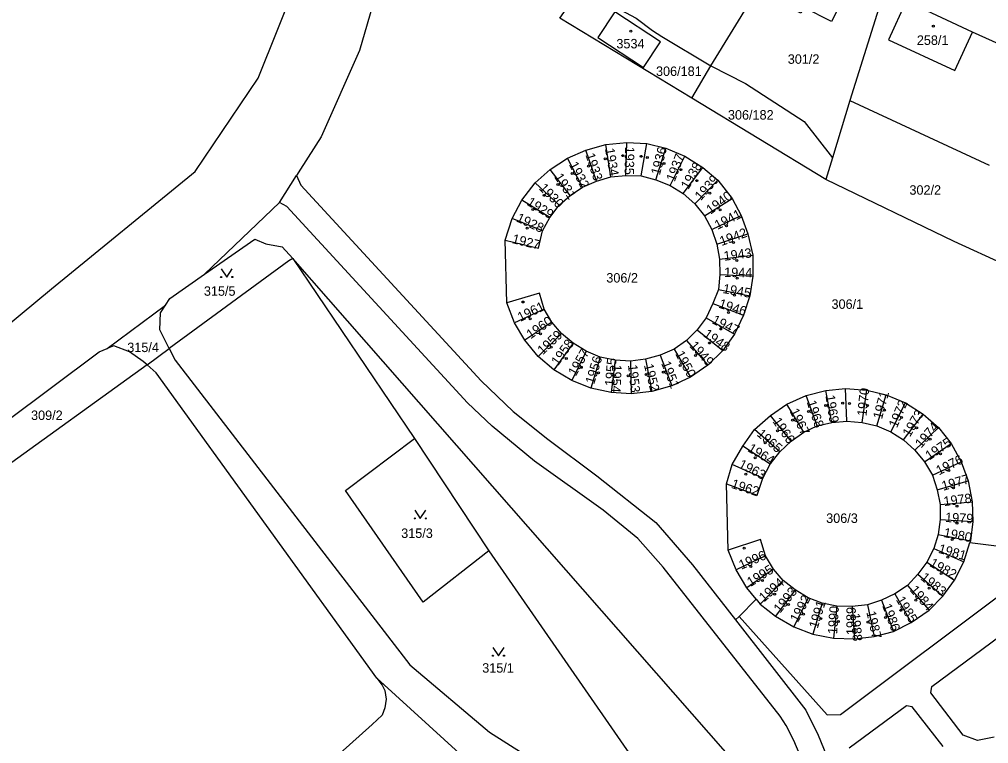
# Model space of a CAD drawing. Extents: x -679220 to -673243, y -1075091 to -1066557.
# Drawn here: x -676420.8 to -676246.6, y -1072425.2 to -1072295.1 of the extents above; entities that cross this region are included whole.
import ezdxf

# ---------------------------------------------------------------- set-up
doc = ezdxf.new("R2010")
doc.units = 0
for name, color, linetype in [('Hranice parcel', 7, 'Continuous'), ('Parcelní čísla', 7, 'Continuous'), ('Vnitřní kresba', 7, 'Continuous'), ('Značky budov', 7, 'Continuous'), ('Značky kultur', 7, 'Continuous')]:
    doc.layers.add(name, color=color, linetype=linetype)

msp = doc.modelspace()

# ---------------------------------------------------------------- linework, layer by layer
at = {"layer": 'Hranice parcel'}
for p, q in [((-676296.48, -1072303.48), (-676279.94, -1072276.36)), ((-676265.34, -1072290.05), (-676271.52, -1072309.71)), ((-676299.9, -1072309.29), (-676296.48, -1072303.48)), ((-676275.84, -1072323.88), (-676299.9, -1072309.29)), ((-676271.52, -1072309.71), (-676274.64, -1072320.01)), ((-676271.52, -1072309.71), (-676246.44, -1072321.34)), ((-676318.98, -1072318.61), (-676315.36, -1072317.62)), ((-676315.36, -1072317.62), (-676311.63, -1072317.26)), ((-676314.48, -1072323.42), (-676315.36, -1072317.62)), ((-676311.78, -1072323.16), (-676311.63, -1072317.26)), ((-676311.63, -1072317.26), (-676308.03, -1072317.42)), ((-676309.05, -1072323.25), (-676308.03, -1072317.42)), ((-676308.03, -1072317.42), (-676304.61, -1072318.29)), ((-676322.27, -1072320.05), (-676318.98, -1072318.61)), ((-676317.08, -1072324.2), (-676318.98, -1072318.61)), ((-676306.38, -1072323.96), (-676304.61, -1072318.29)), ((-676304.61, -1072318.29), (-676301.15, -1072319.7)), ((-676303.8, -1072324.98), (-676301.15, -1072319.7)), ((-676301.15, -1072319.7), (-676297.97, -1072321.71)), ((-676325.36, -1072322.08), (-676322.27, -1072320.05)), ((-676319.56, -1072325.3), (-676322.27, -1072320.05)), ((-676301.46, -1072326.41), (-676297.97, -1072321.71)), ((-676297.97, -1072321.71), (-676295.25, -1072324.04)), ((-676274.64, -1072320.01), (-676275.84, -1072323.88)), ((-676374.02, -1072328.04), (-676370.96, -1072323.19)), ((-676328.06, -1072324.5), (-676325.36, -1072322.08)), ((-676321.78, -1072326.75), (-676325.36, -1072322.08)), ((-676317.08, -1072324.2), (-676314.48, -1072323.42)), ((-676314.48, -1072323.42), (-676311.78, -1072323.16)), ((-676311.78, -1072323.16), (-676309.05, -1072323.25)), ((-676309.05, -1072323.25), (-676306.38, -1072323.96)), ((-676330.46, -1072327.6), (-676328.06, -1072324.5)), ((-676323.78, -1072328.52), (-676328.06, -1072324.5)), ((-676319.56, -1072325.3), (-676317.08, -1072324.2)), ((-676306.38, -1072323.96), (-676303.8, -1072324.98)), ((-676303.8, -1072324.98), (-676301.46, -1072326.41)), ((-676299.4, -1072328.29), (-676295.25, -1072324.04)), ((-676295.25, -1072324.04), (-676292.66, -1072327.28)), ((-676323.78, -1072328.52), (-676321.78, -1072326.75)), ((-676321.78, -1072326.75), (-676319.56, -1072325.3)), ((-676301.46, -1072326.41), (-676299.4, -1072328.29)), ((-676387.5, -1072340.91), (-676374.02, -1072328.04)), ((-676332.24, -1072330.91), (-676330.46, -1072327.6)), ((-676325.42, -1072330.7), (-676330.46, -1072327.6)), ((-676325.42, -1072330.7), (-676323.78, -1072328.52)), ((-676299.4, -1072328.29), (-676297.65, -1072330.43)), ((-676297.65, -1072330.43), (-676292.66, -1072327.28)), ((-676292.66, -1072327.28), (-676291.02, -1072330.35)), ((-676297.65, -1072330.43), (-676296.34, -1072332.88)), ((-676296.34, -1072332.88), (-676291.02, -1072330.35)), ((-676291.02, -1072330.35), (-676289.87, -1072333.63)), ((-676333.48, -1072334.78), (-676332.24, -1072330.91)), ((-676326.76, -1072333.1), (-676332.24, -1072330.91)), ((-676326.76, -1072333.1), (-676325.42, -1072330.7)), ((-676296.34, -1072332.88), (-676295.45, -1072335.51)), ((-676295.45, -1072335.51), (-676289.87, -1072333.63)), ((-676289.87, -1072333.63), (-676288.95, -1072337.48)), ((-676333.18, -1072346.04), (-676333.48, -1072334.78)), ((-676295.45, -1072335.51), (-676294.94, -1072338.2)), ((-676371.63, -1072338.06), (-676349.77, -1072370.44)), ((-676294.94, -1072338.2), (-676288.95, -1072337.48)), ((-676294.94, -1072338.2), (-676294.88, -1072340.96)), ((-676288.95, -1072337.48), (-676288.94, -1072341.24)), ((-676294.88, -1072340.96), (-676295.1, -1072343.67)), ((-676294.88, -1072340.96), (-676288.94, -1072341.24)), ((-676288.94, -1072341.24), (-676289.52, -1072344.81)), ((-676295.1, -1072343.67), (-676296.14, -1072346.19)), ((-676295.1, -1072343.67), (-676289.52, -1072344.81)), ((-676331.8, -1072349.66), (-676333.18, -1072346.04)), ((-676289.52, -1072344.81), (-676290.61, -1072348.27)), ((-676405.02, -1072354.26), (-676394.51, -1072346.45)), ((-676326.44, -1072347.2), (-676331.8, -1072349.66)), ((-676325.07, -1072349.54), (-676326.44, -1072347.2)), ((-676296.14, -1072346.19), (-676297.35, -1072348.76)), ((-676296.14, -1072346.19), (-676290.61, -1072348.27)), ((-676325.07, -1072349.54), (-676329.93, -1072352.76)), ((-676323.33, -1072351.59), (-676325.07, -1072349.54)), ((-676297.35, -1072348.76), (-676298.94, -1072350.92)), ((-676297.35, -1072348.76), (-676292.22, -1072351.69)), ((-676290.61, -1072348.27), (-676292.22, -1072351.69)), ((-676329.93, -1072352.76), (-676331.8, -1072349.66)), ((-676298.94, -1072350.92), (-676300.9, -1072352.8)), ((-676298.94, -1072350.92), (-676294.36, -1072354.59)), ((-676327.55, -1072355.72), (-676329.93, -1072352.76)), ((-676323.33, -1072351.59), (-676327.55, -1072355.72)), ((-676321.27, -1072353.32), (-676323.33, -1072351.59)), ((-676300.9, -1072352.8), (-676303.1, -1072354.36)), ((-676300.9, -1072352.8), (-676297.07, -1072357.27)), ((-676292.22, -1072351.69), (-676294.36, -1072354.59)), ((-676397.84, -1072357.19), (-676393.87, -1072354.27)), ((-676321.27, -1072353.32), (-676324.71, -1072358.08)), ((-676318.93, -1072354.76), (-676321.52, -1072360.01)), ((-676318.93, -1072354.76), (-676321.27, -1072353.32)), ((-676316.39, -1072355.82), (-676318.93, -1072354.76)), ((-676303.1, -1072354.36), (-676305.61, -1072355.45)), ((-676303.1, -1072354.36), (-676300.15, -1072359.43)), ((-676294.36, -1072354.59), (-676297.07, -1072357.27)), ((-676324.71, -1072358.08), (-676327.55, -1072355.72)), ((-676316.39, -1072355.82), (-676318.08, -1072361.39)), ((-676313.71, -1072356.38), (-676316.39, -1072355.82)), ((-676313.71, -1072356.38), (-676314.41, -1072362.17)), ((-676310.96, -1072356.51), (-676313.71, -1072356.38)), ((-676308.24, -1072356.2), (-676310.96, -1072356.51)), ((-676310.96, -1072356.51), (-676310.82, -1072362.38)), ((-676305.61, -1072355.45), (-676308.24, -1072356.2)), ((-676308.24, -1072356.2), (-676307.09, -1072362)), ((-676305.61, -1072355.45), (-676303.5, -1072360.95)), ((-676397.84, -1072357.19), (-676435.06, -1072384.05)), ((-676321.52, -1072360.01), (-676324.71, -1072358.08)), ((-676297.07, -1072357.27), (-676300.15, -1072359.43)), ((-676318.08, -1072361.39), (-676321.52, -1072360.01)), ((-676300.15, -1072359.43), (-676303.5, -1072360.95)), ((-676314.41, -1072362.17), (-676318.08, -1072361.39)), ((-676303.5, -1072360.95), (-676307.09, -1072362)), ((-676279.34, -1072362.68), (-676275.83, -1072361.78)), ((-676275.83, -1072361.78), (-676272.28, -1072361.47)), ((-676274.74, -1072367.56), (-676275.83, -1072361.78)), ((-676272.28, -1072361.47), (-676268.46, -1072361.73)), ((-676272.06, -1072367.32), (-676272.28, -1072361.47)), ((-676269.31, -1072367.55), (-676268.46, -1072361.73)), ((-676268.46, -1072361.73), (-676264.98, -1072362.57)), ((-676310.82, -1072362.38), (-676314.41, -1072362.17)), ((-676307.09, -1072362), (-676310.82, -1072362.38)), ((-676282.82, -1072364.28), (-676279.34, -1072362.68)), ((-676277.37, -1072368.16), (-676279.34, -1072362.68)), ((-676266.64, -1072368.15), (-676264.98, -1072362.57)), ((-676264.98, -1072362.57), (-676261.5, -1072364.04)), ((-676285.77, -1072366.32), (-676282.82, -1072364.28)), ((-676279.78, -1072369.31), (-676282.82, -1072364.28)), ((-676264.16, -1072369.22), (-676261.5, -1072364.04)), ((-676261.5, -1072364.04), (-676258.31, -1072366.06)), ((-676288.65, -1072368.81), (-676285.77, -1072366.32)), ((-676282.08, -1072370.89), (-676285.77, -1072366.32)), ((-676261.87, -1072370.68), (-676258.31, -1072366.06)), ((-676258.31, -1072366.06), (-676255.55, -1072368.47)), ((-676279.78, -1072369.31), (-676277.37, -1072368.16)), ((-676277.37, -1072368.16), (-676274.74, -1072367.56)), ((-676274.74, -1072367.56), (-676272.06, -1072367.32)), ((-676272.06, -1072367.32), (-676269.31, -1072367.55)), ((-676269.31, -1072367.55), (-676266.64, -1072368.15)), ((-676266.64, -1072368.15), (-676264.16, -1072369.22)), ((-676259.81, -1072372.52), (-676255.55, -1072368.47)), ((-676255.55, -1072368.47), (-676253.28, -1072371.33)), ((-676349.77, -1072370.44), (-676336.42, -1072390.58)), ((-676290.72, -1072371.82), (-676288.65, -1072368.81)), ((-676284.1, -1072372.82), (-676288.65, -1072368.81)), ((-676282.08, -1072370.89), (-676279.78, -1072369.31)), ((-676264.16, -1072369.22), (-676261.87, -1072370.68)), ((-676292.64, -1072375.1), (-676290.72, -1072371.82)), ((-676285.82, -1072375.04), (-676290.72, -1072371.82)), ((-676284.1, -1072372.82), (-676282.08, -1072370.89)), ((-676261.87, -1072370.68), (-676259.81, -1072372.52)), ((-676258.12, -1072374.62), (-676253.28, -1072371.33)), ((-676253.28, -1072371.33), (-676251.48, -1072374.61)), ((-676285.82, -1072375.04), (-676284.1, -1072372.82)), ((-676259.81, -1072372.52), (-676258.12, -1072374.62)), ((-676293.7, -1072378.59), (-676292.64, -1072375.1)), ((-676287.13, -1072377.56), (-676292.64, -1072375.1)), ((-676287.13, -1072377.56), (-676285.82, -1072375.04)), ((-676258.12, -1072374.62), (-676256.67, -1072377.02)), ((-676256.67, -1072377.02), (-676251.48, -1072374.61)), ((-676251.48, -1072374.61), (-676250.24, -1072378.06)), ((-676256.67, -1072377.02), (-676255.84, -1072379.62)), ((-676293.4, -1072390.49), (-676293.7, -1072378.59)), ((-676255.84, -1072379.62), (-676250.24, -1072378.06)), ((-676250.24, -1072378.06), (-676249.5, -1072381.78)), ((-676255.84, -1072379.62), (-676255.28, -1072382.29)), ((-676255.28, -1072382.29), (-676249.5, -1072381.78)), ((-676255.28, -1072382.29), (-676255.28, -1072384.95)), ((-676249.5, -1072381.78), (-676249.38, -1072385.33)), ((-676255.28, -1072384.95), (-676255.61, -1072387.66)), ((-676255.28, -1072384.95), (-676249.38, -1072385.33)), ((-676249.38, -1072385.33), (-676249.83, -1072388.83)), ((-676255.61, -1072387.66), (-676256.44, -1072390.2)), ((-676255.61, -1072387.66), (-676249.83, -1072388.83)), ((-676251.04, -1072392.6), (-676249.92, -1072389.1)), ((-676249.83, -1072388.83), (-676249.92, -1072389.1)), ((-676336.42, -1072390.58), (-676286.47, -1072462.64)), ((-676291.97, -1072394.03), (-676293.4, -1072390.49)), ((-676256.44, -1072390.2), (-676257.7, -1072392.66)), ((-676256.44, -1072390.2), (-676251.04, -1072392.6)), ((-676286.69, -1072391.5), (-676291.97, -1072394.03)), ((-676285.21, -1072393.89), (-676286.69, -1072391.5)), ((-676257.7, -1072392.66), (-676259.3, -1072394.78)), ((-676257.7, -1072392.66), (-676252.72, -1072395.87)), ((-676252.72, -1072395.87), (-676251.04, -1072392.6)), ((-676290.01, -1072397.25), (-676291.97, -1072394.03)), ((-676285.21, -1072393.89), (-676290.01, -1072397.25)), ((-676283.5, -1072395.94), (-676285.21, -1072393.89)), ((-676259.3, -1072394.78), (-676261.16, -1072396.82)), ((-676259.3, -1072394.78), (-676254.82, -1072398.74)), ((-676283.5, -1072395.94), (-676287.64, -1072400.19)), ((-676281.34, -1072397.61), (-676283.5, -1072395.94)), ((-676254.82, -1072398.74), (-676252.72, -1072395.87)), ((-676288.34, -1072399.32), (-676290.01, -1072397.25)), ((-676281.34, -1072397.61), (-676284.85, -1072402.35)), ((-676279.03, -1072399.03), (-676281.34, -1072397.61)), ((-676263.41, -1072398.36), (-676265.82, -1072399.49)), ((-676261.16, -1072396.82), (-676263.41, -1072398.36)), ((-676263.41, -1072398.36), (-676260.47, -1072403.46)), ((-676261.16, -1072396.82), (-676257.27, -1072401.26)), ((-676288.34, -1072399.32), (-676287.64, -1072400.19)), ((-676279.03, -1072399.03), (-676281.6, -1072404.26)), ((-676276.49, -1072400.02), (-676279.03, -1072399.03)), ((-676276.49, -1072400.02), (-676278.14, -1072405.57)), ((-676273.86, -1072400.57), (-676276.49, -1072400.02)), ((-676265.82, -1072399.49), (-676268.36, -1072400.32)), ((-676265.82, -1072399.49), (-676263.66, -1072405.07)), ((-676257.27, -1072401.26), (-676254.82, -1072398.74)), ((-676287.64, -1072400.19), (-676284.85, -1072402.35)), ((-676273.86, -1072400.57), (-676274.47, -1072406.28)), ((-676271.12, -1072400.61), (-676273.86, -1072400.57)), ((-676268.36, -1072400.32), (-676271.12, -1072400.61)), ((-676271.12, -1072400.61), (-676270.7, -1072406.4)), ((-676268.36, -1072400.32), (-676267.11, -1072406)), ((-676260.47, -1072403.46), (-676257.27, -1072401.26)), ((-676284.85, -1072402.35), (-676281.6, -1072404.26)), ((-676263.66, -1072405.07), (-676260.47, -1072403.46)), ((-676281.6, -1072404.26), (-676278.14, -1072405.57)), ((-676267.11, -1072406), (-676263.66, -1072405.07)), ((-676278.14, -1072405.57), (-676274.47, -1072406.28)), ((-676274.47, -1072406.28), (-676270.7, -1072406.4)), ((-676270.7, -1072406.4), (-676267.11, -1072406))]:
    msp.add_line(p, q, dxfattribs=at)
for points in [[(-676434.8, -1072359.89), (-676415.01, -1072343.53), (-676389.18, -1072322.47), (-676377.87, -1072305.66), (-676370.95, -1072288.33), (-676368.5, -1072263.86), (-676369.03, -1072238.4), (-676368.85, -1072231.56)], [(-676355.2, -1072271.06), (-676355.48, -1072281.26), (-676356.89, -1072291.18), (-676359.65, -1072300.73), (-676366.57, -1072316.22), (-676370.28, -1072322.02), (-676370.96, -1072323.19)], [(-676284.03, -1072290.85), (-676280.05, -1072282.92), (-676270.81, -1072287.62), (-676274.78, -1072295.52), (-676279.8, -1072293), (-676280.32, -1072294.03), (-676284.52, -1072291.87), (-676284.03, -1072290.85)], [(-676318.7, -1072287.76), (-676318.16, -1072290.47), (-676309.95, -1072294.91), (-676306.99, -1072297.14), (-676305.31, -1072298.18), (-676296.48, -1072303.48)], [(-676299.9, -1072309.29), (-676323.62, -1072294.93), (-676319.41, -1072288.79)], [(-676237.77, -1072302.43), (-676239.53, -1072301.48), (-676239.46, -1072301.35), (-676240.22, -1072300.78), (-676240.55, -1072300.65), (-676241.08, -1072301.17), (-676249.44, -1072297.41), (-676261.36, -1072291.87), (-676263.81, -1072290.74), (-676265.34, -1072290.05)], [(-676308.61, -1072303.77), (-676305.53, -1072299.16), (-676313.77, -1072293.75), (-676316.81, -1072298.4), (-676308.61, -1072303.77)], [(-676296.48, -1072303.48), (-676290.27, -1072306.64), (-676279.7, -1072313.49), (-676274.64, -1072320.01)], [(-676370.96, -1072323.19), (-676370.19, -1072324.92), (-676337.76, -1072360.05), (-676332.05, -1072365.58), (-676325.8, -1072370.56), (-676316.98, -1072377.11), (-676306.39, -1072385.49), (-676299.77, -1072393.11), (-676292.07, -1072402.99)], [(-676243.59, -1072339.2), (-676252.73, -1072335.04), (-676275.84, -1072323.88)], [(-676240.63, -1072470.5), (-676259.07, -1072453.6), (-676261.24, -1072451.54), (-676262.68, -1072450.14), (-676275.53, -1072436.12), (-676276.14, -1072435.29), (-676278.28, -1072431.93), (-676280.47, -1072427.4), (-676281.58, -1072424.69), (-676282.94, -1072421.98), (-676284.05, -1072420.33), (-676305.09, -1072393.55), (-676309.65, -1072388.37), (-676315.86, -1072383.3), (-676328.19, -1072374.47), (-676335.83, -1072368.19), (-676340.22, -1072364.01), (-676372.73, -1072328.75), (-676374.02, -1072328.04)], [(-676333.48, -1072334.78), (-676327.5, -1072336.23), (-676326.76, -1072333.1)], [(-676387.5, -1072340.91), (-676378.49, -1072334.59), (-676376.49, -1072335.46), (-676373.54, -1072335.97), (-676371.63, -1072338.06)], [(-676371.63, -1072338.06), (-676372.39, -1072338.5), (-676393.87, -1072354.27)], [(-676227.86, -1072501.86), (-676299.88, -1072419.89), (-676371.63, -1072338.06)], [(-676394.51, -1072346.45), (-676393.74, -1072345.29), (-676387.5, -1072340.91)], [(-676326.44, -1072347.2), (-676327.31, -1072344.34), (-676333.18, -1072346.04)], [(-676393.87, -1072354.27), (-676395.58, -1072350.93), (-676395.42, -1072347.83), (-676394.51, -1072346.45)], [(-676435.06, -1072384.05), (-676433.01, -1072378.55), (-676430.04, -1072373.48), (-676429.61, -1072372.52), (-676423.37, -1072367.5), (-676406.48, -1072354.84), (-676405.02, -1072354.26)], [(-676397.84, -1072357.19), (-676398.54, -1072356.57), (-676401.01, -1072354.88), (-676403.8, -1072353.77), (-676405.02, -1072354.26)], [(-676393.87, -1072354.27), (-676392.79, -1072356.37), (-676350.62, -1072411.11), (-676336.27, -1072423.2), (-676320.05, -1072433.48), (-676310.5, -1072438.74), (-676297.87, -1072456.58), (-676292.66, -1072479.44), (-676278.01, -1072497.19), (-676240.58, -1072545.43), (-676237.18, -1072549.2), (-676240.15, -1072551.88)], [(-676356.54, -1072413.49), (-676396.23, -1072358.62), (-676397.84, -1072357.19)], [(-676336.42, -1072390.58), (-676348.23, -1072399.81), (-676362.19, -1072379.76), (-676349.77, -1072370.44)], [(-676293.7, -1072378.59), (-676288.16, -1072380.6), (-676287.13, -1072377.56)], [(-676286.69, -1072391.5), (-676287.6, -1072388.58), (-676293.4, -1072390.49)], [(-676249.92, -1072389.1), (-676228.26, -1072391.78), (-676166.55, -1072475.76), (-676169.49, -1072478.01)], [(-676292.07, -1072402.99), (-676291.41, -1072402.41), (-676288.34, -1072399.32)], [(-676292.07, -1072402.99), (-676279.41, -1072419.22), (-676277.22, -1072423.73), (-676275.71, -1072427.4), (-676272.62, -1072432.59), (-676272.04, -1072433.35), (-676258.47, -1072448.08), (-676256.31, -1072450.13), (-676236.39, -1072468.37), (-676234.99, -1072469.86), (-676232.52, -1072472.99), (-676208.52, -1072507.9)], [(-676356.54, -1072413.49), (-676355.6, -1072414.73), (-676355.09, -1072415.72), (-676354.88, -1072417.25), (-676355.09, -1072418.8), (-676355.57, -1072420.11), (-676357.38, -1072421.82), (-676377.07, -1072439.5), (-676378.04, -1072440.21), (-676386.9, -1072428.71), (-676404.85, -1072441.99), (-676414.73, -1072449.5), (-676433.17, -1072463.49), (-676424.44, -1072475.29), (-676425.42, -1072476.09), (-676414.74, -1072490.14), (-676415.99, -1072491.09), (-676414.16, -1072493.47), (-676412.92, -1072492.53), (-676404.02, -1072504.23), (-676430.73, -1072524.26), (-676422.26, -1072535.65), (-676393.2, -1072513.64), (-676382.24, -1072527.95)], [(-676303.18, -1072461.34), (-676310.03, -1072450.02), (-676324.78, -1072438.42), (-676341.09, -1072427.55), (-676356.54, -1072413.49)]]:
    msp.add_lwpolyline(points, dxfattribs=at)
at = {"layer": 'Vnitřní kresba'}
for p, q in [((-676261.36, -1072291.87), (-676264.58, -1072298.79)), ((-676264.58, -1072298.79), (-676252.66, -1072304.33)), ((-676252.66, -1072304.33), (-676249.44, -1072297.41)), ((-676273.2, -1072420.02), (-676240.9, -1072395.77)), ((-676291.41, -1072402.41), (-676275.56, -1072420.05)), ((-676256.76, -1072415.01), (-676244.53, -1072405.96)), ((-676256.97, -1072416.12), (-676256.76, -1072415.01)), ((-676251.13, -1072423.71), (-676256.97, -1072416.12)), ((-676261.34, -1072418.44), (-676271.66, -1072426.06)), ((-676260.31, -1072418.66), (-676261.34, -1072418.44)), ((-676254.74, -1072425.78), (-676260.31, -1072418.66)), ((-676275.56, -1072420.05), (-676273.2, -1072420.02)), ((-676248.55, -1072424.7), (-676251.13, -1072423.71)), ((-676245.59, -1072424.08), (-676248.55, -1072424.7))]:
    msp.add_line(p, q, dxfattribs=at)
at = {"layer": 'Značky budov'}
for centre in [(-676310.88, -1072297.22), (-676256.5, -1072296.36), (-676315.48, -1072320.16), (-676312.34, -1072319.61), (-676309.03, -1072319.73), (-676307.92, -1072319.92), (-676318.48, -1072321.52), (-676304.92, -1072321.02), (-676321.43, -1072322.81), (-676301.91, -1072322.13), (-676324.01, -1072324.77), (-676299.02, -1072324.1), (-676326.46, -1072326.74), (-676296.69, -1072326.37), (-676328.49, -1072329.26), (-676294.85, -1072329.32), (-676293.68, -1072332.23), (-676329.53, -1072332.64), (-676292.42, -1072335.23), (-676291.84, -1072338.47), (-676291.78, -1072341.6), (-676330.27, -1072345.9), (-676292.27, -1072344.67), (-676293.31, -1072347.8), (-676328.99, -1072348.91), (-676294.73, -1072350.75), (-676327.14, -1072351.62), (-676296.76, -1072353.27), (-676325.18, -1072354.01), (-676322.48, -1072356.04), (-676299.27, -1072355.49), (-676319.78, -1072357.64), (-676305.04, -1072358.5), (-676302.04, -1072357.33), (-676316.71, -1072358.62), (-676311.37, -1072359.17), (-676308.11, -1072358.93), (-676275.86, -1072364.51), (-676272.8, -1072364.08), (-676271.59, -1072364.15), (-676268.32, -1072364.51), (-676265.26, -1072365.36), (-676281.83, -1072367.14), (-676278.92, -1072365.58), (-676262.2, -1072366.64), (-676259.5, -1072368.49), (-676284.54, -1072369.06), (-676257.08, -1072370.56), (-676286.74, -1072371.2), (-676288.52, -1072373.9), (-676255.23, -1072373.19), (-676290.23, -1072376.82), (-676253.74, -1072376.18), (-676252.89, -1072379.31), (-676252.25, -1072382.58), (-676252.25, -1072385.64), (-676253.1, -1072388.56), (-676290.51, -1072390.12), (-676253.88, -1072391.76), (-676289.3, -1072393.4), (-676255.09, -1072394.68), (-676287.24, -1072395.96), (-676285.03, -1072398.38), (-676257.23, -1072397.31), (-676282.54, -1072400.23), (-676259.64, -1072399.45), (-676279.84, -1072402.01), (-676262.35, -1072401.3), (-676276.71, -1072402.79), (-676273.58, -1072403.29), (-676268.25, -1072403.43), (-676265.12, -1072402.58)]:
    msp.add_circle(centre, 0.175, dxfattribs=at)
at = {"layer": 'Značky kultur'}
for points in [[(-676384.53, -1072339.92), (-676383.53, -1072341.42), (-676382.53, -1072339.92)], [(-676349.73, -1072383.28), (-676348.73, -1072384.78), (-676347.73, -1072383.28)], [(-676335.68, -1072407.95), (-676334.68, -1072409.45), (-676333.68, -1072407.95)]]:
    msp.add_lwpolyline(points, dxfattribs=at)
for centre in [(-676384.53, -1072341.42), (-676382.53, -1072341.42), (-676349.73, -1072384.78), (-676347.73, -1072384.78), (-676335.68, -1072409.45), (-676333.68, -1072409.45)]:
    msp.add_circle(centre, 0.1, dxfattribs=at)

# ---------------------------------------------------------------- texts
at = {"layer": 'Parcelní čísla'}
for s, p in [('3534', (-676313.48, -1072300.34)), ('258/1', (-676259.47, -1072299.71)), ('301/2', (-676282.67, -1072303.11)), ('306/181', (-676306.36, -1072305.29)), ('306/182', (-676293.43, -1072313.13)), ('302/2', (-676260.8, -1072326.63)), ('306/2', (-676315.29, -1072342.41)), ('315/5', (-676387.64, -1072344.78)), ('306/1', (-676274.81, -1072347.13)), ('315/4', (-676401.41, -1072354.9)), ('309/2', (-676418.71, -1072367.1)), ('306/3', (-676275.77, -1072385.59)), ('315/3', (-676352.17, -1072388.29)), ('315/1', (-676337.6, -1072412.5))]:
    msp.add_text(s, height=1.7, dxfattribs=at).set_placement(p)
for s, rotation, p in [('1935', 269, (-676311.93, -1072317.98)), ('1936', 75, (-676305.68, -1072323.2)), ('1933', 288, (-676319.07, -1072319.45)), ('1934', 280, (-676315.54, -1072318.39)), ('1937', 69, (-676303.01, -1072324.39)), ('1932', 297, (-676322.06, -1072321.2)), ('1938', 60, (-676300.55, -1072325.8)), ('1931', 303, (-676324.72, -1072323.43)), ('1939', 48, (-676298.32, -1072327.79)), ('1930', 314, (-676327.5, -1072325.55)), ('1940', 37, (-676296.54, -1072330.23)), ('1929', 328, (-676329.73, -1072328.37)), ('1928', 335, (-676331.61, -1072331.37)), ('1941', 27, (-676295.31, -1072332.96)), ('1927', 346, (-676332.34, -1072335.3)), ('1942', 20, (-676294.57, -1072335.86)), ('1943', 7, (-676294.09, -1072338.5)), ('1944', 359, (-676294.11, -1072341.4)), ('1945', 350, (-676294.43, -1072344.28)), ('1961', 26, (-676330.75, -1072349.49)), ('1946', 342, (-676295.22, -1072346.89)), ('1960', 35, (-676328.91, -1072352.62)), ('1947', 334, (-676296.44, -1072349.66)), ('1959', 43, (-676326.73, -1072355.49)), ('1948', 325, (-676297.97, -1072352)), ('1958', 54, (-676323.98, -1072357.46)), ('1949', 312, (-676300.44, -1072353.84)), ('1957', 60, (-676320.8, -1072359.34)), ('1950', 298, (-676302.95, -1072355.21)), ('1956', 73, (-676317.48, -1072360.77)), ('1955', 85, (-676313.88, -1072361.08)), ('1951', 291, (-676305.45, -1072356.89)), ('1954', 268, (-676314.23, -1072357.11)), ('1953', 276, (-676311.4, -1072357.23)), ('1952', 284, (-676308.55, -1072357.23)), ('1970', 84, (-676268.53, -1072366.47)), ('1969', 279, (-676275.91, -1072362.72)), ('1971', 75, (-676265.75, -1072367.06)), ('1972', 67, (-676263.05, -1072368.63)), ('1967', 296, (-676282.37, -1072365.5)), ('1968', 288, (-676279.29, -1072363.86)), ('1973', 59, (-676260.72, -1072370.27)), ('1966', 304, (-676285.47, -1072367.34)), ('1974', 49, (-676258.68, -1072372.24)), ('1965', 319, (-676288.37, -1072369.8)), ('1975', 34, (-676257.23, -1072374.39)), ('1964', 329, (-676290.02, -1072372.64)), ('1976', 27, (-676255.48, -1072377.06)), ('1963', 333, (-676291.67, -1072375.59)), ('1977', 16, (-676254.74, -1072379.83)), ('1962', 342, (-676292.96, -1072379.27)), ('1978', 7, (-676254.56, -1072382.57)), ('1979', 357, (-676254.41, -1072385.42)), ('1980', 349, (-676254.74, -1072388.11)), ('1981', 344, (-676255.72, -1072390.94)), ('1996', 23, (-676291.04, -1072394.01)), ('1995', 32, (-676289.35, -1072397.11)), ('1982', 331, (-676257.33, -1072393.29)), ('1983', 321, (-676258.95, -1072395.64)), ('1994', 41, (-676286.96, -1072399.9)), ('1993', 51, (-676284.05, -1072401.9)), ('1984', 310, (-676260.83, -1072397.68)), ('1992', 62, (-676280.87, -1072403.59)), ('1991', 73, (-676277.3, -1072404.67)), ('1985', 301, (-676263.28, -1072399.39)), ('1990', 86, (-676273.81, -1072405.62)), ('1989', 90, (-676270.44, -1072405.74)), ('1987', 283, (-676268.56, -1072401.62)), ('1986', 290, (-676265.72, -1072400.45)), ('1988', 275, (-676271.39, -1072401.88))]:
    msp.add_text(s, height=1.7, rotation=rotation, dxfattribs=at).set_placement(p)

doc.saveas('drawing.dxf')
